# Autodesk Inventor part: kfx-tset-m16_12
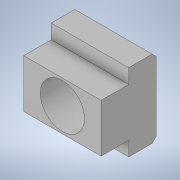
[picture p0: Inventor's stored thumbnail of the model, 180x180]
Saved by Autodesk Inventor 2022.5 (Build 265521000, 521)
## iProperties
Created: 2021-10
Part Number: kfx-tset-m16_12
Material: 一般
Document SubType Name: Modeling
Designer: ImaoCorp
Density: 1 g/cm^3
Appearance: 既定
Author: ImaoCorp
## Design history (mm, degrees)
feature "kfx-tset-m16_12"
node "ソリッド1"
